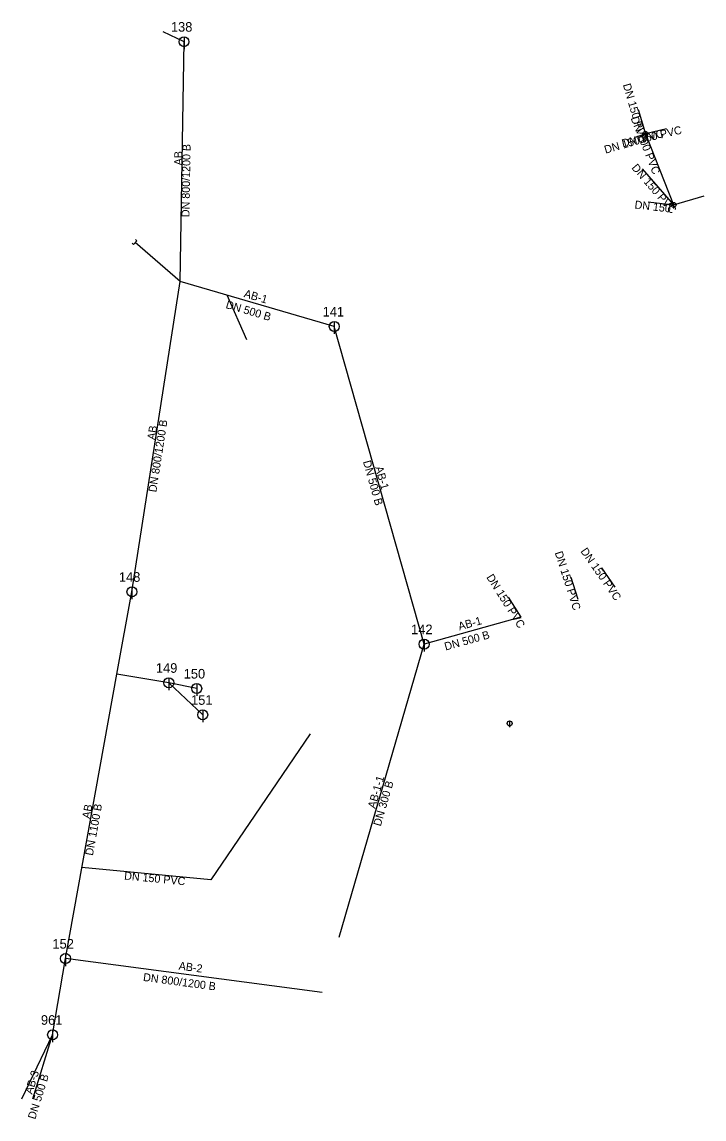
# Model space of a CAD drawing. Extents: x -444530 to -444393, y -1121211 to -1120991.
import ezdxf

# ---------------------------------------------------------------- set-up
doc = ezdxf.new("R2010")
doc.units = 0
for name, color, linetype in [('_odlehcovaci_stoka_smvak_z_dokumentace_', 7, 'Continuous'), ('_pripojka_kanal_destova_priblizne_', 7, 'Continuous'), ('_pripojka_kanal_jednotna_priblizne_', 7, 'Continuous'), ('_pripojka_kanal_splaskova_priblizne_', 7, 'Continuous'), ('_stoka_jednotna_smvak_prevzato_z_dokumentace_', 7, 'Continuous'), ('Default', 7, 'Continuous'), ('MoLevel 119', 7, 'Continuous'), ('MoLevel 120', 7, 'Continuous'), ('MoLevel 124', 7, 'Continuous'), ('MoLevel 128', 7, 'Continuous'), ('MoLevel 55', 7, 'Continuous'), ('MoLevel 57', 7, 'Continuous'), ('MoLevel 60', 7, 'Continuous'), ('MoLevel 68', 7, 'Continuous'), ('MoLevel 69', 7, 'Continuous')]:
    doc.layers.add(name, color=color, linetype=linetype)

# ---------------------------------------------------------------- blocks, each defined once
blk = doc.blocks.new('_vyust_objekt_')
at = {"layer": 'Default'}
blk.add_lwpolyline([(0.00004, 0.00005), (0, 0.00005), (0, -0.00005), (0.00004, -0.00005), (0.00004, -0.00005)], dxfattribs=at)
blk = doc.blocks.new('_sachta_kanal_prip_')
at = {"layer": 'Default'}
blk.add_line((0, 0.00005), (0, -0.000075), dxfattribs=at)
blk.add_circle((0, 0), 0.00005, dxfattribs=at)
blk = doc.blocks.new('_sachta_kanal_prevzato_z_dokumentace_')
at = {"layer": 'Default'}
blk.add_line((0, 0.00005), (0, -0.000075), dxfattribs=at)
blk.add_circle((0, 0), 0.00005, dxfattribs=at)

msp = doc.modelspace()

# ---------------------------------------------------------------- linework, layer by layer
at = {"layer": '_odlehcovaci_stoka_smvak_z_dokumentace_'}
msp.add_line((-444498.04, -1121043.34), (-444507.06, -1121035.58), dxfattribs=at)
at = {"layer": '_pripojka_kanal_destova_priblizne_'}
msp.add_line((-444405.37, -1121020.79), (-444399.11, -1121028.01), dxfattribs=at)
at = {"layer": '_pripojka_kanal_jednotna_priblizne_'}
for p, q in [((-444399.11, -1121028.01), (-444392.99, -1121026.17)), ((-444484.67, -1121055.09), (-444488.59, -1121046.11)), ((-444413.58, -1121100.74), (-444410.85, -1121104.65)), ((-444419.69, -1121102.61), (-444418.28, -1121107.02)), ((-444432.26, -1121106.67), (-444429.74, -1121110.68))]:
    msp.add_line(p, q, dxfattribs=at)
msp.add_lwpolyline([(-444471.95, -1121134.05), (-444491.88, -1121163.31), (-444517.73, -1121160.82)], dxfattribs=at)
at = {"layer": '_pripojka_kanal_splaskova_priblizne_'}
for p, q in [((-444406.17, -1121008.92), (-444404.76, -1121013.79)), ((-444400.5, -1121012.8), (-444404.76, -1121013.79)), ((-444406.5, -1121014.29), (-444404.76, -1121013.79)), ((-444404.76, -1121013.79), (-444399.11, -1121028.01)), ((-444404.21, -1121027.42), (-444399.11, -1121028.01))]:
    msp.add_line(p, q, dxfattribs=at)
at = {"layer": '_stoka_jednotna_smvak_prevzato_z_dokumentace_'}
for p, q in [((-444497.27, -1120995.3), (-444501.42, -1120993.34)), ((-444498.04, -1121043.34), (-444497.27, -1120995.3)), ((-444507.71, -1121105.57), (-444498.04, -1121043.34)), ((-444467.13, -1121052.39), (-444498.04, -1121043.34)), ((-444449.12, -1121116.07), (-444467.13, -1121052.39)), ((-444510.74, -1121122.07), (-444507.71, -1121105.57)), ((-444429.74, -1121110.68), (-444449.12, -1121116.07)), ((-444466.14, -1121174.83), (-444449.12, -1121116.07)), ((-444521.03, -1121179.1), (-444510.74, -1121122.07)), ((-444500.33, -1121123.81), (-444510.74, -1121122.07)), ((-444494.72, -1121124.96), (-444500.33, -1121123.81)), ((-444493.52, -1121130.23), (-444500.33, -1121123.81)), ((-444523.62, -1121194.37), (-444521.03, -1121179.1)), ((-444469.55, -1121185.92), (-444521.03, -1121179.1)), ((-444529.77, -1121207.22), (-444523.62, -1121194.37)), ((-444527.59, -1121207.22), (-444523.62, -1121194.37))]:
    msp.add_line(p, q, dxfattribs=at)

# ---------------------------------------------------------------- block references
at = {"layer": 'MoLevel 119', "xscale": 20000, "yscale": 20000}
for p in [(-444497.27, -1120995.3), (-444467.13, -1121052.39), (-444507.71, -1121105.57), (-444449.12, -1121116.07), (-444500.33, -1121123.81), (-444494.72, -1121124.96), (-444493.52, -1121130.23), (-444521.03, -1121179.1), (-444523.62, -1121194.37)]:
    msp.add_blockref('_sachta_kanal_prevzato_z_dokumentace_', p, dxfattribs=at)
at = {"layer": 'MoLevel 55', "xscale": 9999.999999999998, "yscale": 10000.000000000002, "rotation": 137.927316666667}
msp.add_blockref('_vyust_objekt_', (-444507.06, -1121035.58), dxfattribs=at)
at = {"layer": 'MoLevel 57', "xscale": 10000, "yscale": 10000}
for p in [(-444404.76, -1121013.79), (-444399.11, -1121028.01), (-444431.97, -1121131.96)]:
    msp.add_blockref('_sachta_kanal_prip_', p, dxfattribs=at)

# ---------------------------------------------------------------- texts
at = {"layer": 'MoLevel 120'}
for s, p in [('138', (-444499.89, -1120993.3)), ('141', (-444469.47, -1121050.39)), ('148', (-444510.32, -1121103.57)), ('142', (-444451.73, -1121114.07)), ('149', (-444502.9, -1121121.81)), ('150', (-444497.33, -1121122.96)), ('151', (-444495.86, -1121128.23)), ('152', (-444523.65, -1121177.1)), ('961', (-444525.96, -1121192.37))]:
    msp.add_text(s, height=1.926, dxfattribs=at).set_placement(p)
at = {"layer": 'MoLevel 124'}
for rotation, p in [(287.7756, (-444422.94, -1121097.73)), (304.9153, (-444417.83, -1121097.45)), (302.1772, (-444436.69, -1121102.65)), (354.4922, (-444509.32, -1121163.24))]:
    msp.add_text('DN 150 PVC', height=1.605, rotation=rotation, dxfattribs=at).set_placement(p)
at = {"layer": 'MoLevel 128'}
msp.add_text('DN 150 PVC', height=1.605, rotation=310.9036, dxfattribs=at).set_placement((-444407.62, -1121020.64))
at = {"layer": 'MoLevel 60'}
for s, rotation, p in [('DN 150 PVC', 286.1441, (-444409.28, -1121003.93)), ('DN 200 PVC', 291.648, (-444407.74, -1121010.64)), ('DN 150 PVC', 13.0949, (-444409.29, -1121016.49)), ('DN 150 PVC', 16.0677, (-444412.74, -1121017.76)), ('DN 150', 353.4139, (-444406.98, -1121028.72))]:
    msp.add_text(s, height=1.605, rotation=rotation, dxfattribs=at).set_placement(p)
at = {"layer": 'MoLevel 68'}
for s, height, rotation, p in [('DN 800/1200 B', 1.6049, 89.0869, (-444496.18, -1121030.48)), ('DN 500 B', 1.605, 343.6802, (-444489.02, -1121048.68)), ('DN 800/1200 B', 1.6049, 81.1671, (-444502.83, -1121085.7)), ('DN 500 B', 1.605, 285.792, (-444461.4, -1121079.48)), ('DN 500 B', 1.605, 15.5424, (-444444.81, -1121117.36)), ('DN 300 B', 1.605, 73.8462, (-444457.82, -1121152.68)), ('DN 1100 B', 1.605, 79.7663, (-444515.55, -1121158.55)), ('DN 800/1200 B', 1.6049, 352.4571, (-444505.54, -1121183.57)), ('DN 500 B', 1.605, 72.8162, (-444527.1, -1121211.43))]:
    msp.add_text(s, height=height, rotation=rotation, dxfattribs=at).set_placement(p)
at = {"layer": 'MoLevel 69'}
for s, rotation, p in [('AB', 89.0869, (-444497.65, -1121020.11)), ('AB-1', 343.6802, (-444485.38, -1121046.47)), ('AB', 81.1671, (-444503.08, -1121075.21)), ('AB-1', 285.792, (-444458.96, -1121080.64)), ('AB-1', 15.5424, (-444442.04, -1121113.32)), ('AB-1-1', 73.8462, (-444458.93, -1121149.13)), ('AB', 79.7663, (-444516.13, -1121151.14)), ('AB-2', 352.4571, (-444498.4, -1121181.3)), ('AB-3', 72.8162, (-444527.72, -1121206.4))]:
    msp.add_text(s, height=1.605, rotation=rotation, dxfattribs=at).set_placement(p)

doc.saveas('drawing.dxf')
